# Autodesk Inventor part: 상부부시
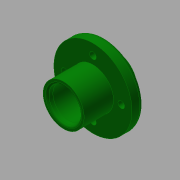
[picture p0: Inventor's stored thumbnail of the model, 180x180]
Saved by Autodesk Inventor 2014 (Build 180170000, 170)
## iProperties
Created: 2015-12
Part Number: 상부부시
Material: 강철, 연강
Document SubType Name: Modeling
Designer: mduedu
Density: 7.86 g/cm^3
Appearance: 진녹색
Author: mduedu
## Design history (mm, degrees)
sketch "스케치1"
  geometry: C1 r 10.5 at (0, 0); C2 r 8 at (0, 0); 1 further point
  constraints: 2 centre point, 2 coincident
  dimensions: "d1" = 21 diameter of C1; "d3" = 16 diameter of C2
extrude "돌출1" new body sketch "스케치1" distance "d4" = 12; taper "d6" = 0 deg; dims "d5" = 15, "d7" = 0
sketch "스케치2"
  geometry: C1 r 20 at (0, 0); C2 r 10.5 at (0, 0) reference; 1 further point
  constraints: 1 centre point, 1 coincident
  dimensions: "d8" = 40 diameter of C1
extrude "돌출2" join sketch "스케치2" distance "d10" = 6; taper "d11" = 0 deg
chamfer "모따기1" distance "d12" = 2.5; stored, may be unused: second distance "d13" = 2, angle "d14" = 10 deg
chamfer "모따기2" distance "d15" = 2.5; stored, may be unused: second distance "d16" = 2, angle "d17" = 10 deg
fillet "모깎기1" dims "d18" = 1
fillet "모깎기2" dims "d19" = 2
sketch "스케치3" dims "d20" = 29
  geometry: 6 further points
  constraints: 2 vertical alignment, 1 coincident, 7 other
  dimensions: "d24" = 360 deg dimension on point (0, 0) point (0, 14.5) (derived)
sketch "스케치4"
  geometry: 4 further points
hole "구멍1" sketch "스케치4" at (-14.5, 0), (0, -14.5), (14.5, 0), (0, 14.5) diameter "d26" = 3.4; stored, may be unused: countersink angle "d30" = 90 deg, drill point angle "d32" = 0 deg; dims "d27" = 6, "d28" = 6.5, "d29" = 3.4, "d31" = 8
fillet "모깎기3" dims "d33" = 1
node "솔리드1"
